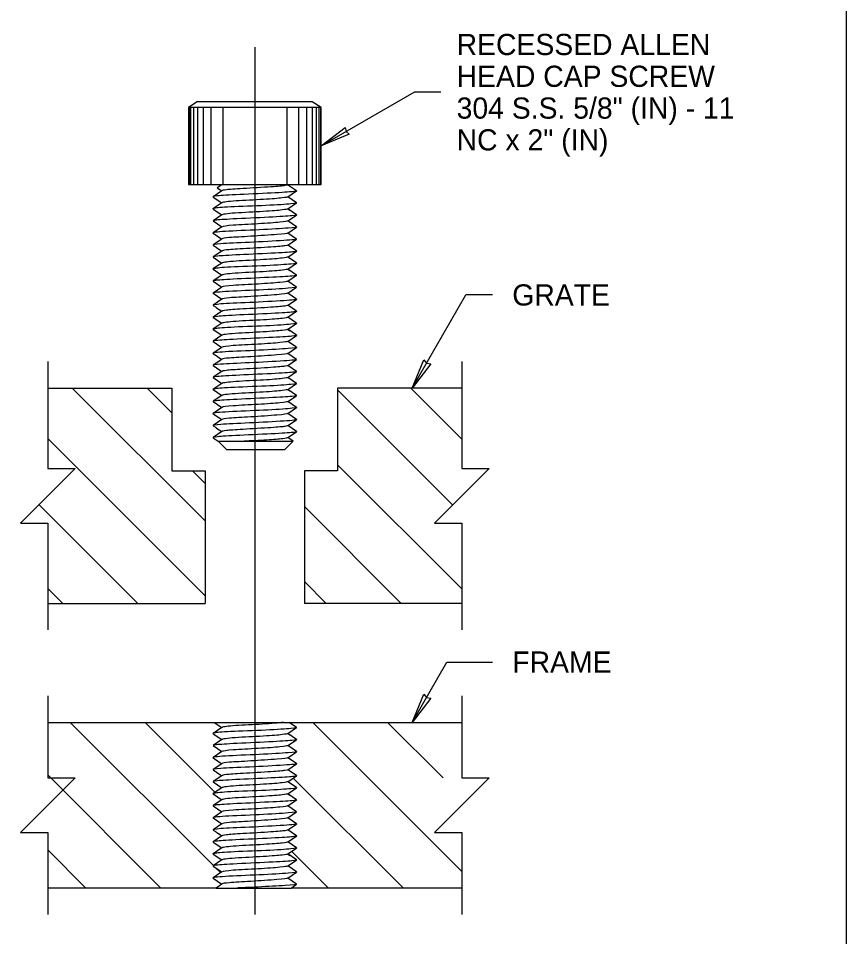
# Model space of a CAD drawing. Extents: x 99862 to 103151, y 100000 to 102076.
# Drawn here: x 102526 to 103151, y 100926 to 101620 of the extents above; entities that cross this region are included whole.
import ezdxf

# ---------------------------------------------------------------- set-up
doc = ezdxf.new("R2010")
doc.units = 0
for name, color, linetype in [('Level 1', 7, 'Continuous'), ('Level 14', 7, 'Continuous'), ('Level 15', 7, 'Continuous'), ('Level 17', 7, 'Continuous'), ('Level 2', 7, 'Continuous'), ('Level 20', 7, 'Continuous')]:
    doc.layers.add(name, color=color, linetype=linetype)

msp = doc.modelspace()

# ---------------------------------------------------------------- linework, layer by layer
at = {"layer": 'Level 1'}
for p, q in [((102673.71, 101087.88), (102679.39, 101084.06)), ((102735.82, 101084.12), (102730.2, 101087.88)), ((102679.39, 101084.06), (102672.72, 101079.63)), ((102672.87, 101079.39), (102679.42, 101075)), ((102729.08, 101079.5), (102735.82, 101083.97)), ((102735.75, 101075.02), (102729.08, 101079.5)), ((102679.42, 101075), (102672.75, 101070.59)), ((102729.15, 101070.41), (102735.82, 101074.81)), ((102672.75, 101070.37), (102679.45, 101065.88)), ((102679.45, 101065.88), (102672.75, 101061.42)), ((102729.09, 101061.28), (102735.82, 101065.79)), ((102735.82, 101065.93), (102729.15, 101070.41)), ((102672.75, 101061.21), (102679.42, 101056.73)), ((102735.82, 101056.77), (102729.09, 101061.28)), ((102679.42, 101056.73), (102672.81, 101052.33)), ((102729.2, 101052.19), (102735.82, 101056.62)), ((102735.82, 101047.75), (102729.2, 101052.19)), ((102679.45, 101047.7), (102672.81, 101043.24)), ((102729.15, 101043.13), (102735.82, 101047.61)), ((102679.39, 101038.61), (102672.72, 101034.17)), ((102672.81, 101043.02), (102679.39, 101038.61)), ((102729.08, 101034.04), (102735.82, 101038.52)), ((102735.82, 101038.66), (102729.15, 101043.13)), ((102672.87, 101033.93), (102679.42, 101029.54)), ((102735.75, 101029.57), (102729.08, 101034.04)), ((102679.42, 101029.54), (102672.75, 101025.13)), ((102672.75, 101024.92), (102679.45, 101020.42)), ((102729.15, 101024.95), (102735.82, 101029.35)), ((102735.82, 101020.48), (102729.15, 101024.95)), ((102679.45, 101020.42), (102672.75, 101015.97)), ((102729.09, 101015.82), (102735.82, 101020.33)), ((102672.75, 101015.75), (102679.42, 101011.27)), ((102679.42, 101011.27), (102672.81, 101006.88)), ((102735.82, 101011.32), (102729.09, 101015.82)), ((102729.2, 101006.73), (102735.82, 101011.17)), ((102735.82, 101002.3), (102729.2, 101006.73)), ((102679.45, 101002.24), (102672.81, 100997.79)), ((102672.81, 100997.57), (102679.39, 100993.16)), ((102729.15, 100997.68), (102735.82, 101002.15)), ((102735.82, 100993.21), (102729.15, 100997.68)), ((102679.39, 100993.16), (102672.72, 100988.72)), ((102729.08, 100988.59), (102735.82, 100993.06)), ((102679.42, 100984.09), (102672.75, 100979.68)), ((102672.87, 100988.48), (102679.42, 100984.09)), ((102735.75, 100984.12), (102729.08, 100988.59)), ((102729.15, 100979.5), (102735.82, 100983.9)), ((102672.75, 100979.46), (102679.45, 100974.97)), ((102679.45, 100974.97), (102672.75, 100970.52)), ((102735.82, 100975.02), (102729.15, 100979.5)), ((102672.75, 100970.3), (102679.42, 100965.82)), ((102729.09, 100970.37), (102735.82, 100974.88)), ((102735.82, 100965.86), (102729.09, 100970.37)), ((102679.42, 100965.82), (102675, 100962.88)), ((102731.59, 100962.88), (102735.82, 100965.72))]:
    msp.add_line(p, q, dxfattribs=at)
msp.add_lwpolyline([(99862, 99999.5), (103151, 99999.5), (103151, 102075.5), (99862, 102075.5)], close=True, dxfattribs=at)
for points in [[(102672.81, 101052.12), (102674.52, 101050.95), (102675.15, 101050.59)], [(102675.4, 101050.37), (102679.45, 101047.7)], [(102672.81, 101006.66), (102674.52, 101005.5), (102675.15, 101005.13)], [(102675.4, 101004.92), (102679.45, 101002.24)]]:
    msp.add_lwpolyline(points, dxfattribs=at)
at = {"layer": 'Level 14'}
for p, q in [((102660.83, 101556.63), (102654.25, 101552.22)), ((102754.25, 101552.22), (102654.25, 101552.22)), ((102654.64, 101552.22), (102654.64, 101494.13)), ((102655.84, 101552.22), (102655.84, 101494.13)), ((102657.9, 101552.22), (102657.9, 101494.13)), ((102660.95, 101552.22), (102660.95, 101494.13)), ((102665.22, 101552.22), (102665.22, 101494.13)), ((102671.18, 101552.22), (102671.18, 101494.13)), ((102680.04, 101552.22), (102680.04, 101494.13)), ((102728.46, 101552.22), (102728.46, 101494.13)), ((102737.32, 101552.22), (102737.32, 101494.13)), ((102743.28, 101552.22), (102743.28, 101494.13)), ((102747.55, 101552.22), (102747.55, 101494.13)), ((102754.25, 101552.22), (102747.67, 101556.63)), ((102750.6, 101552.22), (102750.6, 101494.13)), ((102752.66, 101552.22), (102752.66, 101494.13)), ((102753.86, 101552.22), (102753.86, 101494.13)), ((102679.45, 101489.32), (102672.81, 101484.86)), ((102679.45, 101493.95), (102675.97, 101491.62)), ((102728.98, 101493.95), (102679.45, 101493.95)), ((102735.82, 101489.37), (102728.98, 101493.95)), ((102729.15, 101484.75), (102735.82, 101489.23)), ((102672.81, 101484.64), (102679.39, 101480.23)), ((102735.82, 101480.28), (102729.15, 101484.75)), ((102679.39, 101480.23), (102672.68, 101475.77)), ((102672.87, 101475.55), (102679.42, 101471.16)), ((102729.08, 101475.66), (102735.82, 101480.13)), ((102735.75, 101471.19), (102729.08, 101475.66)), ((102679.42, 101471.16), (102672.75, 101466.75)), ((102729.15, 101466.57), (102735.82, 101470.97)), ((102672.75, 101466.53), (102679.45, 101462.04)), ((102679.45, 101462.04), (102672.75, 101457.59)), ((102729.09, 101457.44), (102735.82, 101461.95)), ((102735.82, 101462.1), (102729.15, 101466.57)), ((102672.75, 101457.37), (102679.42, 101452.89)), ((102735.82, 101452.93), (102729.09, 101457.44)), ((102679.42, 101452.89), (102672.81, 101448.5)), ((102729.2, 101448.35), (102735.82, 101452.79)), ((102735.82, 101443.92), (102729.2, 101448.35)), ((102679.45, 101443.86), (102672.81, 101439.41)), ((102729.15, 101439.3), (102735.82, 101443.77)), ((102679.39, 101434.77), (102672.68, 101430.32)), ((102672.81, 101439.19), (102679.39, 101434.77)), ((102729.08, 101430.21), (102735.82, 101434.68)), ((102735.82, 101434.83), (102729.15, 101439.3)), ((102679.42, 101425.7), (102672.75, 101421.3)), ((102672.87, 101430.1), (102679.42, 101425.7)), ((102735.75, 101425.73), (102729.08, 101430.21)), ((102672.75, 101421.08), (102679.45, 101416.59)), ((102729.15, 101421.12), (102735.82, 101425.52)), ((102735.82, 101416.64), (102729.15, 101421.12)), ((102679.45, 101416.59), (102672.75, 101412.13)), ((102672.75, 101411.92), (102679.42, 101407.44)), ((102729.09, 101411.99), (102735.82, 101416.5)), ((102735.82, 101407.48), (102729.09, 101411.99)), ((102679.42, 101407.44), (102672.81, 101403.04)), ((102729.2, 101402.9), (102735.82, 101407.33)), ((102679.45, 101398.41), (102672.81, 101393.95)), ((102729.15, 101393.84), (102735.82, 101398.32)), ((102735.82, 101398.46), (102729.2, 101402.9)), ((102672.81, 101393.73), (102679.39, 101389.32)), ((102735.82, 101389.37), (102729.15, 101393.84)), ((102679.39, 101389.32), (102672.68, 101384.86)), ((102672.87, 101384.64), (102679.42, 101380.25)), ((102729.08, 101384.75), (102735.82, 101389.23)), ((102735.75, 101380.28), (102729.08, 101384.75)), ((102679.42, 101380.25), (102672.75, 101375.84)), ((102729.15, 101375.66), (102735.82, 101380.06)), ((102672.75, 101375.63), (102679.45, 101371.13)), ((102679.45, 101371.13), (102672.75, 101366.68)), ((102729.09, 101366.53), (102735.82, 101371.04)), ((102735.82, 101371.19), (102729.15, 101375.66)), ((102672.75, 101366.46), (102679.42, 101361.98)), ((102735.82, 101362.03), (102729.09, 101366.53)), ((102679.42, 101361.98), (102672.81, 101357.59)), ((102729.2, 101357.44), (102735.82, 101361.88)), ((102735.82, 101353.01), (102729.2, 101357.44)), ((102679.45, 101352.95), (102672.81, 101348.5)), ((102729.15, 101348.39), (102735.82, 101352.86)), ((102679.39, 101343.87), (102672.68, 101339.41)), ((102672.81, 101348.28), (102679.39, 101343.87)), ((102729.08, 101339.3), (102735.82, 101343.77)), ((102735.82, 101343.92), (102729.15, 101348.39)), ((102672.87, 101339.19), (102679.42, 101334.8)), ((102735.75, 101334.83), (102729.08, 101339.3)), ((102679.42, 101334.8), (102672.75, 101330.39)), ((102672.75, 101330.17), (102679.45, 101325.68)), ((102729.15, 101330.21), (102735.82, 101334.61)), ((102735.82, 101325.73), (102729.15, 101330.21)), ((102679.45, 101325.68), (102672.75, 101321.23)), ((102729.09, 101321.08), (102735.82, 101325.59)), ((102672.75, 101321.01), (102679.42, 101316.53)), ((102679.42, 101316.53), (102672.81, 101312.13)), ((102735.82, 101316.57), (102729.09, 101321.08)), ((102729.2, 101311.99), (102735.82, 101316.43)), ((102735.82, 101307.55), (102729.2, 101311.99)), ((102679.45, 101307.5), (102672.81, 101303.04)), ((102672.81, 101302.83), (102676.72, 101300.2)), ((102729.15, 101302.93), (102735.82, 101307.41)), ((102733.22, 101300.2), (102729.15, 101302.93)), ((102676.72, 101300.2), (102733.22, 101300.2)), ((102682.97, 101293.95), (102676.72, 101300.2)), ((102726.97, 101293.95), (102733.22, 101300.2)), ((102673.71, 101087.88), (102730.2, 101087.88)), ((102675, 100962.88), (102731.59, 100962.88))]:
    msp.add_line(p, q, dxfattribs=at)
for points in [[(102654.25, 101552.22), (102654.25, 101494.13), (102680.04, 101494.13)], [(102747.67, 101556.63), (102660.83, 101556.63)], [(102754.25, 101494.13), (102754.25, 101552.22)], [(102675.97, 101491.62), (102679.45, 101489.32)], [(102729.25, 101494.13), (102754.25, 101494.13)], [(102729.17, 101475.6), (102730.69, 101474.61)], [(102672.81, 101448.28), (102674.52, 101447.12), (102675.15, 101446.75), (102675.4, 101446.53), (102679.45, 101443.86)], [(102729.17, 101430.15), (102730.69, 101429.15)], [(102672.81, 101402.83), (102674.52, 101401.66), (102675.15, 101401.3), (102675.4, 101401.08), (102679.45, 101398.41)], [(102729.17, 101384.7), (102730.69, 101383.7)], [(102672.81, 101357.37), (102674.52, 101356.21), (102675.15, 101355.84), (102675.4, 101355.63), (102679.45, 101352.95)], [(102729.17, 101339.24), (102730.69, 101338.24)], [(102672.81, 101311.92), (102674.52, 101310.75), (102675.15, 101310.39), (102675.4, 101310.17), (102679.45, 101307.5)], [(102682.97, 101293.95), (102726.97, 101293.95)], [(102729.17, 101079.44), (102730.69, 101078.44)], [(102729.17, 101033.99), (102730.69, 101032.99)], [(102729.17, 100988.53), (102730.69, 100987.53)]]:
    msp.add_lwpolyline(points, dxfattribs=at)
for points in [[(102735.82, 101489.37), (102735.94, 101489.3), (102735.82, 101488.79), (102723.1, 101487.84), (102690.14, 101486.39), (102673.51, 101485.44), (102672.56, 101484.79), (102672.81, 101484.64)], [(102728.98, 101493.73), (102728.98, 101493.73), (102728.29, 101493.3), (102719.05, 101492.35), (102693.24, 101490.9), (102681.22, 101490.1), (102679.77, 101489.52), (102679.64, 101489.44)], [(102728.92, 101484.64), (102728.79, 101484.57), (102726.71, 101483.99), (102712.47, 101482.75), (102687.99, 101481.73), (102680.21, 101480.72), (102679.58, 101480.35)], [(102735.82, 101480.28), (102736.07, 101480.13), (102734.17, 101479.55), (102714.69, 101478.17), (102682.36, 101477.15), (102672.24, 101476.06), (102672.62, 101475.55), (102672.68, 101475.55)], [(102728.92, 101475.55), (102728.79, 101475.48), (102726.71, 101474.9), (102712.47, 101473.66), (102687.17, 101472.57), (102679.45, 101471.55), (102679.45, 101471.12)], [(102735.82, 101471.19), (102736.07, 101471.04), (102734.74, 101470.46), (102717.34, 101469.44), (102684.58, 101467.92), (102672.56, 101467.12), (102672.62, 101466.61), (102672.75, 101466.53)], [(102735.82, 101462.1), (102736.19, 101461.88), (102732.59, 101461.23), (102708.49, 101459.77), (102678.82, 101458.68), (102672.12, 101457.81), (102672.75, 101457.37)], [(102728.92, 101466.46), (102728.6, 101466.24), (102725.25, 101465.66), (102707.6, 101464.35), (102685.72, 101463.33), (102680.15, 101462.53), (102679.64, 101462.17)], [(102729.05, 101457.44), (102729.11, 101457.08), (102723.42, 101456.43), (102700.26, 101454.83), (102683.19, 101454.03), (102680.02, 101453.3), (102679.71, 101453.08)], [(102735.82, 101452.93), (102736.38, 101452.57), (102729.36, 101451.92), (102699.13, 101450.24), (102675.59, 101449.37), (102672.37, 101448.57), (102672.81, 101448.28)], [(102728.98, 101448.28), (102728.98, 101448.28), (102728.29, 101447.84), (102719.05, 101446.9), (102693.24, 101445.44), (102681.22, 101444.64), (102679.77, 101444.06), (102679.64, 101443.99)], [(102735.82, 101443.92), (102735.94, 101443.84), (102735.82, 101443.33), (102723.1, 101442.39), (102690.14, 101440.93), (102673.51, 101439.99), (102672.56, 101439.33), (102672.81, 101439.19)], [(102735.82, 101434.83), (102736.07, 101434.68), (102734.17, 101434.1), (102714.69, 101432.72), (102682.36, 101431.7), (102672.24, 101430.61), (102672.62, 101430.1), (102672.68, 101430.1)], [(102728.92, 101439.19), (102728.79, 101439.12), (102726.71, 101438.53), (102712.47, 101437.3), (102687.99, 101436.28), (102680.21, 101435.26), (102679.58, 101434.9)], [(102735.82, 101425.73), (102736.07, 101425.59), (102734.74, 101425.01), (102717.34, 101423.99), (102684.58, 101422.46), (102672.56, 101421.66), (102672.62, 101421.15), (102672.75, 101421.08)], [(102728.92, 101430.1), (102728.79, 101430.03), (102726.71, 101429.44), (102712.47, 101428.21), (102687.17, 101427.12), (102679.45, 101426.1), (102679.45, 101425.66)], [(102728.92, 101421.01), (102728.6, 101420.79), (102725.25, 101420.21), (102707.6, 101418.9), (102685.72, 101417.88), (102680.15, 101417.08), (102679.64, 101416.72)], [(102735.82, 101416.64), (102736.19, 101416.43), (102732.59, 101415.77), (102708.49, 101414.32), (102678.82, 101413.23), (102672.12, 101412.35), (102672.75, 101411.92)], [(102729.05, 101411.99), (102729.11, 101411.63), (102723.42, 101410.97), (102700.26, 101409.37), (102683.19, 101408.57), (102680.02, 101407.84), (102679.71, 101407.63)], [(102735.82, 101407.48), (102736.38, 101407.12), (102729.36, 101406.46), (102699.13, 101404.79), (102675.59, 101403.92), (102672.37, 101403.12), (102672.81, 101402.83)], [(102735.82, 101398.46), (102735.94, 101398.39), (102735.82, 101397.88), (102723.1, 101396.93), (102690.14, 101395.48), (102673.51, 101394.53), (102672.56, 101393.88), (102672.81, 101393.73)], [(102728.98, 101402.83), (102728.98, 101402.83), (102728.29, 101402.39), (102719.05, 101401.44), (102693.24, 101399.99), (102681.22, 101399.19), (102679.77, 101398.61), (102679.64, 101398.53)], [(102728.92, 101393.73), (102728.79, 101393.66), (102726.71, 101393.08), (102712.47, 101391.84), (102687.99, 101390.83), (102680.21, 101389.81), (102679.58, 101389.44)], [(102735.82, 101389.37), (102736.07, 101389.23), (102734.17, 101388.64), (102714.69, 101387.26), (102682.36, 101386.24), (102672.24, 101385.15), (102672.62, 101384.64), (102672.68, 101384.64)], [(102728.92, 101384.64), (102728.79, 101384.57), (102726.71, 101383.99), (102712.47, 101382.75), (102687.17, 101381.66), (102679.45, 101380.64), (102679.45, 101380.21)], [(102735.82, 101380.28), (102736.07, 101380.13), (102734.74, 101379.55), (102717.34, 101378.53), (102684.58, 101377.01), (102672.56, 101376.21), (102672.62, 101375.7), (102672.75, 101375.63)], [(102735.82, 101371.19), (102736.19, 101370.97), (102732.59, 101370.32), (102708.49, 101368.86), (102678.82, 101367.77), (102672.12, 101366.9), (102672.75, 101366.46)], [(102728.92, 101375.55), (102728.6, 101375.33), (102725.25, 101374.75), (102707.6, 101373.44), (102685.72, 101372.43), (102680.15, 101371.63), (102679.64, 101371.26)], [(102729.05, 101366.53), (102729.11, 101366.17), (102723.42, 101365.52), (102700.26, 101363.92), (102683.19, 101363.12), (102680.02, 101362.39), (102679.71, 101362.17)], [(102735.82, 101362.03), (102736.38, 101361.66), (102729.36, 101361.01), (102699.13, 101359.33), (102675.59, 101358.46), (102672.37, 101357.66), (102672.81, 101357.37)], [(102728.98, 101357.37), (102728.98, 101357.37), (102728.29, 101356.93), (102719.05, 101355.99), (102693.24, 101354.53), (102681.22, 101353.73), (102679.77, 101353.15), (102679.64, 101353.08)], [(102735.82, 101353.01), (102735.94, 101352.93), (102735.82, 101352.43), (102723.1, 101351.48), (102690.14, 101350.03), (102673.51, 101349.08), (102672.56, 101348.43), (102672.81, 101348.28)], [(102735.82, 101343.92), (102736.07, 101343.77), (102734.17, 101343.19), (102714.69, 101341.81), (102682.36, 101340.79), (102672.24, 101339.7), (102672.62, 101339.19), (102672.68, 101339.19)], [(102728.92, 101348.28), (102728.79, 101348.21), (102726.71, 101347.63), (102712.47, 101346.39), (102687.99, 101345.37), (102680.21, 101344.35), (102679.58, 101343.99)], [(102728.92, 101339.19), (102728.79, 101339.12), (102726.71, 101338.53), (102712.47, 101337.3), (102687.17, 101336.21), (102679.45, 101335.19), (102679.45, 101334.75)], [(102735.82, 101334.83), (102736.07, 101334.68), (102734.74, 101334.1), (102717.34, 101333.08), (102684.58, 101331.55), (102672.56, 101330.75), (102672.62, 101330.24), (102672.75, 101330.17)], [(102728.92, 101330.1), (102728.6, 101329.88), (102725.25, 101329.3), (102707.6, 101327.99), (102685.72, 101326.97), (102680.15, 101326.17), (102679.64, 101325.81)], [(102735.82, 101325.73), (102736.19, 101325.52), (102732.59, 101324.86), (102708.49, 101323.41), (102678.82, 101322.32), (102672.12, 101321.44), (102672.75, 101321.01)], [(102735.82, 101316.57), (102736.38, 101316.21), (102729.36, 101315.55), (102699.13, 101313.88), (102675.59, 101313.01), (102672.37, 101312.21), (102672.81, 101311.92)], [(102729.05, 101321.08), (102729.11, 101320.72), (102723.42, 101320.06), (102700.26, 101318.46), (102683.19, 101317.66), (102680.02, 101316.93), (102679.71, 101316.72)], [(102728.98, 101311.92), (102728.98, 101311.92), (102728.29, 101311.48), (102719.05, 101310.53), (102693.24, 101309.08), (102681.22, 101308.28), (102679.77, 101307.7), (102679.64, 101307.63)], [(102735.82, 101307.55), (102735.94, 101307.48), (102735.82, 101306.97), (102723.1, 101306.03), (102690.14, 101304.57), (102673.51, 101303.63), (102672.56, 101302.97), (102672.81, 101302.83)], [(102728.92, 101302.83), (102728.79, 101302.75), (102726.71, 101302.17), (102714.54, 101301.11), (102701.04, 101300.47), (102696.15, 101300.2)], [(102725.8, 101087.88), (102722.63, 101087.48), (102710.93, 101086.52), (102687.99, 101085.57), (102680.21, 101084.55), (102679.58, 101084.19)], [(102735.82, 101084.12), (102736.07, 101083.97), (102734.17, 101083.39), (102714.69, 101082.01), (102682.36, 101080.99), (102672.24, 101079.9), (102672.62, 101079.39), (102672.68, 101079.39)], [(102728.92, 101079.39), (102728.79, 101079.32), (102726.71, 101078.73), (102712.47, 101077.5), (102687.17, 101076.41), (102679.45, 101075.39), (102679.45, 101074.95)], [(102735.82, 101075.02), (102736.07, 101074.88), (102734.74, 101074.3), (102717.34, 101073.28), (102684.58, 101071.75), (102672.56, 101070.95), (102672.62, 101070.44), (102672.75, 101070.37)], [(102735.82, 101065.93), (102736.19, 101065.72), (102732.59, 101065.06), (102708.49, 101063.61), (102678.82, 101062.52), (102672.12, 101061.64), (102672.75, 101061.21)], [(102728.92, 101070.3), (102728.6, 101070.08), (102725.25, 101069.5), (102707.6, 101068.19), (102685.72, 101067.17), (102680.15, 101066.37), (102679.64, 101066.01)], [(102729.05, 101061.28), (102729.11, 101060.92), (102723.42, 101060.26), (102700.26, 101058.66), (102683.19, 101057.86), (102680.02, 101057.13), (102679.71, 101056.92)], [(102735.82, 101056.77), (102736.38, 101056.41), (102729.36, 101055.75), (102699.13, 101054.08), (102675.59, 101053.21), (102672.37, 101052.41), (102672.81, 101052.12)], [(102728.98, 101052.12), (102728.98, 101052.12), (102728.29, 101051.68), (102719.05, 101050.73), (102693.24, 101049.28), (102681.22, 101048.48), (102679.77, 101047.9), (102679.64, 101047.82)], [(102735.82, 101047.75), (102735.94, 101047.68), (102735.82, 101047.17), (102723.1, 101046.22), (102690.14, 101044.77), (102673.51, 101043.82), (102672.56, 101043.17), (102672.81, 101043.02)], [(102735.82, 101038.66), (102736.07, 101038.52), (102734.17, 101037.93), (102714.69, 101036.55), (102682.36, 101035.53), (102672.24, 101034.44), (102672.62, 101033.93), (102672.68, 101033.93)], [(102728.92, 101043.02), (102728.79, 101042.95), (102726.71, 101042.37), (102712.47, 101041.13), (102687.99, 101040.12), (102680.21, 101039.1), (102679.58, 101038.73)], [(102728.92, 101033.93), (102728.79, 101033.86), (102726.71, 101033.28), (102712.47, 101032.04), (102687.17, 101030.95), (102679.45, 101029.93), (102679.45, 101029.5)], [(102735.82, 101029.57), (102736.07, 101029.42), (102734.74, 101028.84), (102717.34, 101027.82), (102684.58, 101026.3), (102672.56, 101025.5), (102672.62, 101024.99), (102672.75, 101024.92)], [(102728.92, 101024.84), (102728.6, 101024.62), (102725.25, 101024.04), (102707.6, 101022.73), (102685.72, 101021.72), (102680.15, 101020.92), (102679.64, 101020.55)], [(102735.82, 101020.48), (102736.19, 101020.26), (102732.59, 101019.61), (102708.49, 101018.15), (102678.82, 101017.06), (102672.12, 101016.19), (102672.75, 101015.75)], [(102735.82, 101011.32), (102736.38, 101010.95), (102729.36, 101010.3), (102699.13, 101008.62), (102675.59, 101007.75), (102672.37, 101006.95), (102672.81, 101006.66)], [(102729.05, 101015.82), (102729.11, 101015.46), (102723.42, 101014.81), (102700.26, 101013.21), (102683.19, 101012.41), (102680.02, 101011.68), (102679.71, 101011.46)], [(102728.98, 101006.66), (102728.98, 101006.66), (102728.29, 101006.22), (102719.05, 101005.28), (102693.24, 101003.82), (102681.22, 101003.02), (102679.77, 101002.44), (102679.64, 101002.37)], [(102735.82, 101002.3), (102735.94, 101002.22), (102735.82, 101001.72), (102723.1, 101000.77), (102690.14, 100999.32), (102673.51, 100998.37), (102672.56, 100997.72), (102672.81, 100997.57)], [(102728.92, 100997.57), (102728.79, 100997.5), (102726.71, 100996.92), (102712.47, 100995.68), (102687.99, 100994.66), (102680.21, 100993.64), (102679.58, 100993.28)], [(102735.82, 100993.21), (102736.07, 100993.06), (102734.17, 100992.48), (102714.69, 100991.1), (102682.36, 100990.08), (102672.24, 100988.99), (102672.62, 100988.48), (102672.68, 100988.48)], [(102735.82, 100984.12), (102736.07, 100983.97), (102734.74, 100983.39), (102717.34, 100982.37), (102684.58, 100980.84), (102672.56, 100980.04), (102672.62, 100979.53), (102672.75, 100979.46)], [(102728.92, 100988.48), (102728.79, 100988.41), (102726.71, 100987.82), (102712.47, 100986.59), (102687.17, 100985.5), (102679.45, 100984.48), (102679.45, 100984.04)], [(102735.82, 100975.02), (102736.19, 100974.81), (102732.59, 100974.15), (102708.49, 100972.7), (102678.82, 100971.61), (102672.12, 100970.73), (102672.75, 100970.3)], [(102728.92, 100979.39), (102728.6, 100979.17), (102725.25, 100978.59), (102707.6, 100977.28), (102685.72, 100976.26), (102680.15, 100975.46), (102679.64, 100975.1)], [(102729.05, 100970.37), (102729.11, 100970.01), (102723.42, 100969.35), (102700.26, 100967.75), (102683.19, 100966.95), (102680.02, 100966.22), (102679.71, 100966.01)], [(102735.82, 100965.86), (102736.38, 100965.5), (102729.36, 100964.84), (102706.14, 100963.56), (102693.62, 100963.01), (102690.75, 100962.88)]]:
    msp.add_open_spline(points, degree=3, dxfattribs=at)
at = {"layer": 'Level 15'}
for p, q in [((102704.25, 101597.87), (102704.25, 100942.88)), ((102754.25, 101523.17), (102824.62, 101563.8)), ((102844.62, 101563.8), (102824.62, 101563.8)), ((102823.02, 101340.32), (102863.64, 101410.68)), ((102883.64, 101410.68), (102863.64, 101410.68)), ((102823.02, 101087.88), (102849.34, 101133.47)), ((102849.34, 101133.47), (102883.64, 101133.47))]:
    msp.add_line(p, q, dxfattribs=at)
for points in [[(102754.25, 101523.17), (102772.53, 101537.17), (102773.11, 101534.06), (102775.51, 101532)], [(102823.02, 101340.32), (102831.85, 101361.58), (102833.9, 101359.17), (102837.02, 101358.59)], [(102823.02, 101087.88), (102831.85, 101109.14), (102833.9, 101106.73), (102837.02, 101106.16)]]:
    msp.add_lwpolyline(points, close=True, dxfattribs=at)
for points in [[(102547.98, 101360.32), (102547.98, 101279.71), (102568.63, 101279.71), (102527.34, 101238.42), (102547.98, 101238.42), (102547.98, 101157.82)], [(102860.52, 101360.32), (102860.52, 101279.71), (102881.16, 101279.71), (102839.87, 101238.42), (102860.52, 101238.42), (102860.52, 101157.82)], [(102547.98, 101107.88), (102547.98, 101046.03), (102568.63, 101046.03), (102527.34, 101004.73), (102547.98, 101004.73), (102547.98, 100942.88)], [(102860.52, 101107.88), (102860.52, 101046.03), (102881.16, 101046.03), (102839.87, 101004.73), (102860.52, 101004.73), (102860.52, 100942.88)]]:
    msp.add_lwpolyline(points, dxfattribs=at)
at = {"layer": 'Level 17'}
for p, q in [((102666.75, 101240.05), (102566.48, 101340.32)), ((102641.75, 101321.62), (102623.05, 101340.32)), ((102853.6, 101252.15), (102766.75, 101339)), ((102860.52, 101301.8), (102822.01, 101340.32)), ((102666.75, 101183.48), (102547.98, 101302.25)), ((102860.52, 101188.67), (102766.75, 101282.43)), ((102666.75, 101268.33), (102657.27, 101277.82)), ((102615.85, 101177.82), (102541.29, 101252.37)), ((102814.8, 101177.82), (102741.75, 101250.87)), ((102758.23, 101177.82), (102741.75, 101194.3)), ((102559.28, 101177.82), (102547.98, 101189.11)), ((102564.94, 101087.88), (102673.03, 100979.79)), ((102621.5, 101087.88), (102674.32, 101035.07)), ((102747.97, 101087.88), (102860.52, 100975.33)), ((102804.53, 101087.88), (102846.39, 101046.03)), ((102547.98, 101048.26), (102633.37, 100962.88)), ((102733.33, 101045.94), (102816.4, 100962.88)), ((102677.27, 101003.83), (102679.11, 101001.99)), ((102547.98, 100991.7), (102576.8, 100962.88)), ((102732.15, 100990.56), (102759.83, 100962.88)), ((102674.4, 100978.41), (102678.51, 100974.31)), ((102547.98, 100963.41), (102548.51, 100962.88))]:
    msp.add_line(p, q, dxfattribs=at)
at = {"layer": 'Level 2'}
for p, q in [((102547.98, 101340.32), (102641.75, 101340.32)), ((102641.75, 101340.32), (102641.75, 101277.82)), ((102766.75, 101340.32), (102766.75, 101277.82)), ((102860.52, 101340.32), (102766.75, 101340.32)), ((102641.75, 101277.82), (102666.75, 101277.82)), ((102666.75, 101277.82), (102666.75, 101177.82)), ((102766.75, 101277.82), (102741.75, 101277.82)), ((102741.75, 101277.82), (102741.75, 101177.82)), ((102547.98, 101177.82), (102666.75, 101177.82)), ((102860.52, 101177.82), (102741.75, 101177.82)), ((102547.98, 101087.88), (102673.71, 101087.88)), ((102730.2, 101087.88), (102860.52, 101087.88)), ((102675, 100962.88), (102547.98, 100962.88)), ((102860.52, 100962.88), (102731.59, 100962.88))]:
    msp.add_line(p, q, dxfattribs=at)

# ---------------------------------------------------------------- texts
at = {"layer": 'Level 20'}
for s, p in [('RECESSED ALLEN', (102856.62, 101591.8)), ('HEAD CAP SCREW', (102856.62, 101567.8)), ('304 S.S. 5/8" (IN) - 11', (102856.62, 101543.8)), ('NC x 2" (IN)', (102856.62, 101519.8)), ('GRATE', (102898.63, 101402.69)), ('FRAME', (102898.63, 101125.47))]:
    msp.add_text(s, height=16, rotation=360, dxfattribs=at).set_placement(p)

doc.saveas('drawing.dxf')
